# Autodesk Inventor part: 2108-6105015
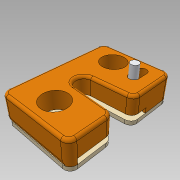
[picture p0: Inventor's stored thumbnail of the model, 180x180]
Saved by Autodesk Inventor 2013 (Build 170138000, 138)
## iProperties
Created: 2012-10
Part Number: 2108-6105015
Material: Thermoplastic Resin
Document SubType Name: Modeling
Designer: VMuser
Density: 1.28 g/cm^3
Mass: 66.2996 g
Surface Area: 208.418 cm^2
Volume: 51.7966 cm^3
Author: VMuser
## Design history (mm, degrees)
derived "2108-6105015.iam"
body "Solid1"
node "Housing 1.ipt:1" dims "d0" = 10
node "Housing 2.ipt:1" dims "d0" = 10
node "axis.ipt:1" dims "d0" = 10
node "2108-6105015.iam_Bodies" dims "d0" = 10
